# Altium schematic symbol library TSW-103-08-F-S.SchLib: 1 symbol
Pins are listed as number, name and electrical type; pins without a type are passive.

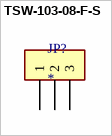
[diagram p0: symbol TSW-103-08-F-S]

## TSW-103-08-F-S
designator JP?
MP: TSW-103-08-F-S
footprint TSW-103-08-F-S
pins: 1, 2, 3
